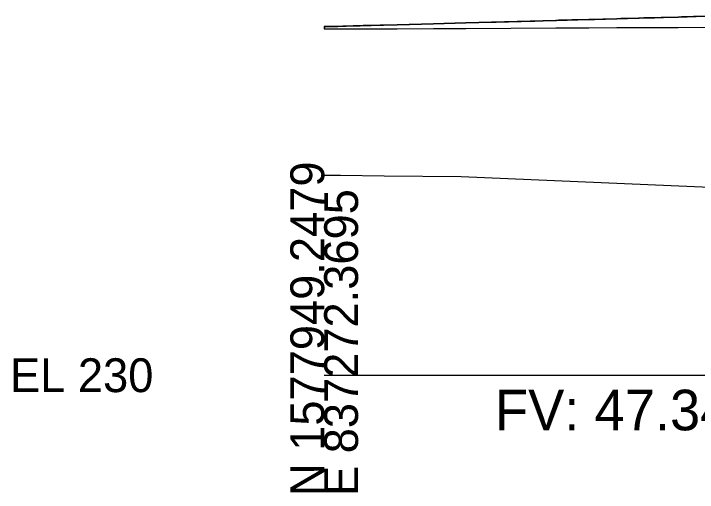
# Model space of a CAD drawing. Extents: x -26 to 303, y -16 to 6048.
# Drawn here: x -25.7 to 30.9, y 5990.3 to 6029.9 of the extents above; entities that cross this region are included whole.
import ezdxf

# ---------------------------------------------------------------- set-up
doc = ezdxf.new("R2010")
doc.units = 0
for name, color, linetype in [('Draft_XS_Grid', 7, 'Continuous'), ('DTM_X_GROUND', 7, 'Continuous'), ('XS_CELL', 7, 'Continuous'), ('XS_M_SHAPES_EARTHWORK', 7, 'Continuous'), ('XS_P_GROUND', 7, 'Continuous'), ('XS_P_SUBGRADE_GRANULAR', 7, 'Continuous'), ('XS_SHEET_EW_TX_VOLUME', 7, 'Continuous')]:
    doc.layers.add(name, color=color, linetype=linetype)

msp = doc.modelspace()

# ---------------------------------------------------------------- linework, layer by layer
at = {"layer": 'DTM_X_GROUND'}
for points in [[(0, 6028.852), (1.531, 6028.892), (3.213, 6028.937), (6.026, 6029.012), (7.059, 6029.04), (9.05, 6029.094), (9.895, 6029.117), (11.71, 6029.166), (13.878, 6029.225), (19.171, 6029.369), (19.221, 6029.37), (19.385, 6029.374), (19.554, 6029.379), (20.106, 6029.394), (20.499, 6029.405), (21.893, 6029.443), (22.361, 6029.456), (24.214, 6029.507), (24.532, 6029.515), (25.995, 6029.556), (26.069, 6029.558), (26.456, 6029.568), (26.894, 6029.58), (29.292, 6029.646), (29.568, 6029.654), (31.534, 6029.708)], [(0, 6016.56), (1.34, 6016.547), (4.962, 6016.503), (11.333, 6016.44), (36.428, 6015.365), (36.445, 6015.366), (38.521, 6015.406), (40.261, 6015.44), (41.739, 6015.469), (69.286, 6014.527), (77.777, 6014.513), (78.789, 6014.517), (79.749, 6014.521), (83.233, 6014.422), (116.875, 6015.983)]]:
    msp.add_lwpolyline(points, dxfattribs=at)
at = {"layer": 'XS_CELL'}
msp.add_line((0, 6000), (150, 6000), dxfattribs=at)
at = {"layer": 'XS_M_SHAPES_EARTHWORK'}
msp.add_lwpolyline([(31.534, 6029.708), (29.568, 6029.654), (29.292, 6029.646), (26.894, 6029.58), (26.456, 6029.568), (26.069, 6029.558), (25.995, 6029.556), (24.532, 6029.515), (24.214, 6029.507), (22.361, 6029.456), (21.893, 6029.443), (20.499, 6029.405), (20.106, 6029.394), (19.554, 6029.379), (19.385, 6029.374), (19.221, 6029.37), (19.171, 6029.369), (13.878, 6029.225), (11.71, 6029.166), (9.895, 6029.117), (9.05, 6029.094), (7.059, 6029.04), (6.026, 6029.012), (3.213, 6028.937), (1.531, 6028.892), (0, 6028.852), (0, 6028.659), (1.531, 6028.665), (6.026, 6028.683), (9.05, 6028.697), (11.71, 6028.709), (19.171, 6028.743), (19.391, 6028.744), (20.106, 6028.747), (21.893, 6028.756), (24.214, 6028.767), (25.995, 6028.775), (26.456, 6028.778), (29.292, 6028.792), (31.534, 6028.803)], dxfattribs=at)
for points in [[(21.893, 6029.443), (22.361, 6029.456), (24.214, 6029.507)], [(26.456, 6029.568), (26.894, 6029.58), (29.292, 6029.646)], [(1.531, 6028.892), (3.213, 6028.937), (6.026, 6029.012)], [(6.026, 6029.012), (7.059, 6029.04), (9.05, 6029.094)], [(9.05, 6029.094), (9.895, 6029.117), (11.71, 6029.166)], [(11.71, 6029.166), (13.878, 6029.225), (19.171, 6029.368)], [(20.106, 6029.394), (20.499, 6029.405), (21.893, 6029.443)]]:
    msp.add_lwpolyline(points, close=True, dxfattribs=at)
at = {"layer": 'XS_P_GROUND'}
for points in [[(0, 6028.851), (1.531, 6028.892), (6.026, 6029.012), (9.05, 6029.094), (11.71, 6029.166), (19.171, 6029.368), (19.391, 6029.374), (20.106, 6029.394), (21.893, 6029.443), (24.214, 6029.507), (25.995, 6029.555), (26.456, 6029.568), (29.292, 6029.646), (31.534, 6029.708), (32.079, 6029.723), (39.326, 6029.925)], [(0, 6028.846), (0.12, 6028.849), (1.123, 6028.876), (2.531, 6028.914), (2.71, 6028.918), (2.978, 6028.925), (4.835, 6028.975), (7.559, 6029.049), (7.635, 6029.051), (7.762, 6029.054), (9.577, 6029.104), (12.546, 6029.185), (12.56, 6029.185), (12.586, 6029.186), (14.237, 6029.231), (17.33, 6029.315), (17.416, 6029.317), (17.614, 6029.323), (18.518, 6029.348), (20.566, 6029.404), (20.995, 6029.415), (22.114, 6029.446), (22.251, 6029.45), (22.64, 6029.461), (23.75, 6029.491), (26.897, 6029.578), (26.967, 6029.58), (27.237, 6029.588), (27.324, 6029.59), (27.667, 6029.6), (28.474, 6029.622), (31.68, 6029.711)]]:
    msp.add_lwpolyline(points, dxfattribs=at)
at = {"layer": 'XS_P_SUBGRADE_GRANULAR'}
msp.add_lwpolyline([(0, 6028.659), (1.531, 6028.665), (6.026, 6028.683), (9.05, 6028.697), (11.71, 6028.709), (19.171, 6028.743), (19.391, 6028.744), (20.106, 6028.747), (21.893, 6028.756), (24.214, 6028.767), (25.995, 6028.775), (26.456, 6028.778), (29.292, 6028.792), (31.534, 6028.803)], dxfattribs=at)

# ---------------------------------------------------------------- texts
at = {"layer": 'Draft_XS_Grid'}
msp.add_text('-', height=0.0001, dxfattribs=at).set_placement((0, 6000))
at = {"layer": 'XS_CELL'}
for s, p in [('N 1577949.2479', (0, 5990)), ('E 837272.3695', (2.8, 5990))]:
    msp.add_text(s, height=2.8, rotation=90, dxfattribs=at).set_placement(p)
msp.add_text('EL 230', height=2.8, dxfattribs=at).set_placement((-26, 5998.6))
at = {"layer": 'XS_SHEET_EW_TX_VOLUME'}
msp.add_text('FV: 47.34 CY', height=3.36, dxfattribs=at).set_placement((14.13, 5995.44))

doc.saveas('drawing.dxf')
